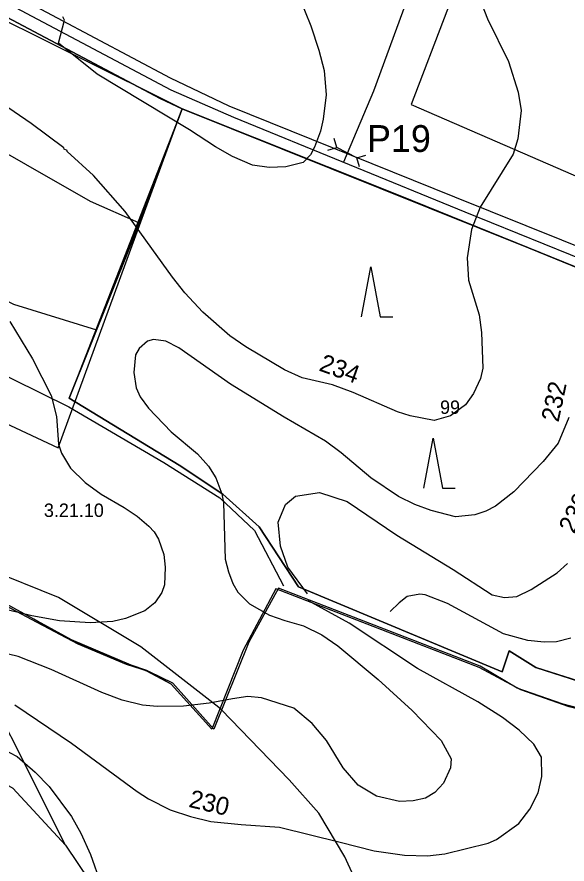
# Model space of a CAD drawing. Extents: x -662500 to -655523, y -1056000 to -1049993.
# Drawn here: x -659796.6 to -659489.3, y -1053594 to -1053120.4 of the extents above; entities that cross this region are included whole.
import ezdxf

# ---------------------------------------------------------------- set-up
doc = ezdxf.new("R2010")
doc.units = 0
for name, color, linetype in [('58', 7, 'Continuous'), ('63LINIE', 7, 'Continuous'), ('Vrstva 1', 7, 'Continuous'), ('Vrstva 15', 7, 'Continuous'), ('Vrstva 24', 7, 'Continuous'), ('Vrstva 37', 7, 'Continuous'), ('Vrstva 5', 7, 'Continuous'), ('Vrstva 61', 7, 'Continuous'), ('Vrstva 7', 7, 'Continuous'), ('Vrstva 9', 7, 'Continuous')]:
    doc.layers.add(name, color=color, linetype=linetype)

msp = doc.modelspace()

# ---------------------------------------------------------------- linework, layer by layer
at = {"layer": '58'}
msp.add_lwpolyline([(-659349.05, -1053610.31), (-659382.28, -1053593.05), (-659417.22, -1053580.42), (-659433.92, -1053582.96), (-659461.02, -1053573.16), (-659482.43, -1053565.41), (-659473.54, -1053538.79), (-659468.08, -1053510.71), (-659491.48, -1053504.57), (-659517.22, -1053495.65), (-659537.81, -1053483.36), (-659650.49, -1053439.77), (-659667.03, -1053469.94), (-659686.62, -1053518.64), (-659709.63, -1053492.85), (-659722.57, -1053486.62), (-659735.51, -1053482.41), (-659762.47, -1053471.11), (-659788.5, -1053457.32), (-659816.61, -1053442.42)], dxfattribs=at)
at = {"layer": '63LINIE'}
msp.add_lwpolyline([(-660157.65, -1052847.13), (-660132.52, -1052869.51), (-660111.66, -1052892.24), (-660084.95, -1052921), (-660069.74, -1052937.89), (-660023.99, -1052984.81), (-660006.51, -1053000.13), (-659985.6, -1053013.28), (-659850.42, -1053086.91), (-659781.9, -1053123.24), (-659710.72, -1053161.03), (-659675.58, -1053176.35), (-659546.48, -1053229.26), (-659428.67, -1053277.07), (-659332.46, -1053315.26), (-659288.19, -1053334.01)], dxfattribs=at)
at = {"layer": 'Vrstva 1'}
for points in [[(-659408.81, -1053315), (-659357.31, -1053379.54), (-659371.42, -1053421.26), (-659397.36, -1053408.04), (-659415.14, -1053443.98), (-659395.43, -1053476.68), (-659396.96, -1053511.86), (-659473.07, -1053494.87), (-659506.81, -1053484.14), (-659521.74, -1053474.81), (-659525.6, -1053486.6), (-659639.42, -1053438.92), (-659661.41, -1053405.48), (-659681.61, -1053387.18), (-659705.99, -1053371.05), (-659767.42, -1053333.48), (-659733.08, -1053247.59), (-659704.27, -1053171.81)], [(-659704.27, -1053171.81), (-659649.81, -1053193.58), (-659510.84, -1053249.48), (-659447.27, -1053275.33), (-659454.8, -1053293.04), (-659408.81, -1053315)], [(-659352.7, -1053608.59), (-659382.31, -1053593.57), (-659400.19, -1053586.69), (-659419.88, -1053580.04), (-659433.72, -1053582.64), (-659469.23, -1053570.77), (-659483.99, -1053565.83), (-659475.92, -1053539.11), (-659469.8, -1053510.83), (-659488.11, -1053506.12), (-659515.11, -1053496.67), (-659538.49, -1053484.19), (-659651.93, -1053440.19), (-659670.2, -1053474.39), (-659687.83, -1053518.62), (-659710.54, -1053493.35), (-659724.05, -1053486.09), (-659732.76, -1053482.89), (-659763.85, -1053469.82), (-659766.11, -1053468.58), (-659784.94, -1053458.3), (-659787.26, -1053457.03), (-659804.8, -1053447.45)]]:
    msp.add_lwpolyline(points, dxfattribs=at)
at = {"layer": 'Vrstva 15'}
for points in [[(-659491.47, -1052600.22), (-659560.64, -1052733.92), (-659579.45, -1052789.58), (-659610.72, -1052846.89), (-659556.93, -1052891.69), (-659532.56, -1052924.18), (-659546.19, -1053014.6), (-659577.15, -1053106.27), (-659597.46, -1053161.91), (-659614.21, -1053201.5)], [(-660065.03, -1053195.42), (-659955.25, -1053245.75), (-659767.64, -1053338.31), (-659714.66, -1053369.5), (-659683.23, -1053389.22), (-659663.87, -1053407.49), (-659647.8, -1053438.49)]]:
    msp.add_lwpolyline(points, dxfattribs=at)
at = {"layer": 'Vrstva 24'}
for points in [[(-659728.49, -1053235.51), (-659755.5, -1053223.5), (-659901.5, -1053140), (-659970.5, -1053087.5), (-659990.5, -1053068), (-660000, -1053060.67), (-660008, -1053054.5), (-660026.5, -1053036.5), (-660039.5, -1053009.5), (-660040.38, -1053000), (-660042, -1052982.5), (-660034, -1052954)], [(-660081, -1053315.5), (-660096, -1053300), (-660112, -1053273), (-660119.5, -1053246), (-660118.5, -1053214.5), (-660111.5, -1053187.5), (-660090.5, -1053151.5), (-660075, -1053138), (-660060, -1053131), (-660044.5, -1053128), (-660018, -1053135), (-660007, -1053141.5), (-660000, -1053147.33), (-659995, -1053151.5), (-659934, -1053205.5), (-659879, -1053241.5), (-659798.5, -1053281), (-659752.13, -1053295.23)], [(-659728.49, -1053235.51), (-659704.27, -1053171.81), (-659510.84, -1053249.48), (-659447.27, -1053275.33), (-659454.8, -1053293.04), (-659408.81, -1053315), (-659357.31, -1053379.54)], [(-659752.13, -1053295.23), (-659733.08, -1053247.59), (-659728.49, -1053235.51)], [(-659478.7, -1053493.08), (-659506.81, -1053484.14), (-659521.74, -1053474.81), (-659525.6, -1053486.6), (-659639.42, -1053438.92), (-659661.41, -1053405.48), (-659681.61, -1053387.18), (-659705.99, -1053371.05), (-659767.42, -1053333.48), (-659752.13, -1053295.23)], [(-659547, -1053857), (-659553, -1053835), (-659577.5, -1053700), (-659592, -1053637), (-659613.5, -1053590), (-659628, -1053565.5), (-659644.5, -1053547), (-659682.5, -1053507.5), (-659683.92, -1053506.4), (-659727.5, -1053472.5), (-659773.5, -1053445), (-659853, -1053413), (-659885, -1053404.5)], [(-659769.5, -1053583.5), (-659830.5, -1053462), (-659842, -1053442.5), (-659850.5, -1053432.5), (-659861, -1053420.5), (-659881.56, -1053406.8), (-659885, -1053404.5)], [(-660267, -1053453), (-660245, -1053457.5), (-660181.5, -1053447.5), (-660160, -1053446.5), (-660126.5, -1053449), (-660086, -1053456), (-660070, -1053459.5), (-660043.5, -1053470), (-660010, -1053485.5), (-660000, -1053490.5), (-659990, -1053495.5), (-659964, -1053526), (-659956.84, -1053531.01), (-659954, -1053533), (-659924.5, -1053540.5), (-659867, -1053533), (-659839, -1053534), (-659815, -1053542.5), (-659799, -1053551.5), (-659769.5, -1053583.5)], [(-659769.5, -1053583.5), (-659703.5, -1053681.5), (-659687, -1053701.5)]]:
    msp.add_lwpolyline(points, dxfattribs=at)
at = {"layer": 'Vrstva 37'}
for points in [[(-660026.32, -1052991.73), (-660026.32, -1053058.37), (-660035.43, -1053154.64), (-660050.23, -1053231.54), (-659773.69, -1053361.27), (-659704.27, -1053171.81), (-659884.58, -1053081.65)], [(-659536.53, -1053064.71), (-659576.38, -1053169.38), (-659333.28, -1053275.05), (-659323.04, -1053211.82), (-659365.73, -1053099.03)]]:
    msp.add_lwpolyline(points, close=True, dxfattribs=at)
at = {"layer": 'Vrstva 5'}
for points in [[(-659937.32, -1052850.73), (-659969.58, -1052873.81), (-659986.59, -1052886.79), (-659995.64, -1052898.4), (-660031.07, -1052952.12), (-660039.24, -1052962.1), (-660004.2, -1052995.1), (-659978.55, -1053011.07), (-659877.72, -1053065.47), (-659795.26, -1053109.44), (-659710.99, -1053154.41), (-659678.33, -1053170.13), (-659552.14, -1053220.98), (-659353.83, -1053300.67), (-659328.92, -1053309.76), (-659307.52, -1053281.7), (-659380.3, -1053101.02), (-659414.22, -1052998.59), (-659429.64, -1052959.69), (-659439.55, -1052923.56), (-659442.36, -1052874.55), (-659444.11, -1052845.81)], [(-659877.72, -1053065.47), (-659795.26, -1053109.44), (-659710.99, -1053154.41), (-659678.33, -1053170.13), (-659552.14, -1053220.98), (-659353.83, -1053300.67), (-659328.92, -1053309.76), (-659331.19, -1053313.18), (-659314.63, -1053326.76), (-659289.39, -1053339.57), (-659294.69, -1053337.55), (-659360.48, -1053311.02), (-659451.61, -1053273.55), (-659582.56, -1053220.47), (-659704.27, -1053171.81), (-659716.54, -1053165.89), (-659802.22, -1053120.51)], [(-659802.22, -1053120.51), (-659716.54, -1053165.89), (-659704.27, -1053171.81), (-659767.42, -1053333.48), (-659705.99, -1053371.05), (-659681.61, -1053387.18), (-659661.41, -1053405.48), (-659639.42, -1053438.92), (-659525.6, -1053486.6), (-659521.74, -1053474.81), (-659506.81, -1053484.14), (-659473.07, -1053494.87)], [(-659604.21, -1053288.05), (-659598.96, -1053260.05), (-659593.71, -1053288.05), (-659586.71, -1053288.05)], [(-659354.31, -1053607.7), (-659382.31, -1053593.57), (-659419.88, -1053580.04), (-659433.72, -1053582.64), (-659483.99, -1053565.83), (-659475.92, -1053539.11), (-659469.8, -1053510.83), (-659488.11, -1053506.12), (-659515.11, -1053496.67), (-659538.49, -1053484.19), (-659651.93, -1053440.19), (-659670.2, -1053474.39), (-659687.83, -1053518.62), (-659710.54, -1053493.35), (-659724.01, -1053485.82), (-659732.76, -1053482.89), (-659766.11, -1053468.58), (-659838.26, -1053429.18)]]:
    msp.add_lwpolyline(points, dxfattribs=at)
msp.add_lwpolyline([(-659704.27, -1053171.81), (-659733.08, -1053247.59), (-659767.42, -1053333.48), (-659705.99, -1053371.05), (-659681.61, -1053387.18), (-659661.41, -1053405.48), (-659639.42, -1053438.92), (-659525.6, -1053486.6), (-659521.74, -1053474.81), (-659506.81, -1053484.14), (-659473.07, -1053494.87), (-659428.79, -1053504.91), (-659396.96, -1053511.86), (-659395.43, -1053476.68), (-659415.14, -1053443.98), (-659397.36, -1053408.04), (-659371.42, -1053421.26), (-659357.31, -1053379.54), (-659408.81, -1053315), (-659454.8, -1053293.04), (-659447.27, -1053275.33), (-659451.61, -1053273.55), (-659510.84, -1053249.48), (-659582.56, -1053220.47)], close=True, dxfattribs=at)
at = {"layer": 'Vrstva 61'}
for points in [[(-659622.91, -1053194.86), (-659617.84, -1053193.31), (-659619.39, -1053188.24)], [(-659606.81, -1053199.18), (-659617.84, -1053193.31)], [(-659605.26, -1053204.26), (-659606.81, -1053199.18), (-659601.73, -1053197.63)]]:
    msp.add_lwpolyline(points, dxfattribs=at)
at = {"layer": 'Vrstva 7'}
for p, q in [((-659638.85, -1053109.45), (-659632.47, -1053125.32)), ((-659537.19, -1053112.86), (-659533.77, -1053121.4)), ((-659773.39, -1053135.1), (-659770.08, -1053122.21)), ((-659770.08, -1053122.21), (-659771.07, -1053120.22)), ((-659533.77, -1053121.4), (-659521.95, -1053145.32)), ((-659632.47, -1053125.32), (-659627.94, -1053138.93)), ((-659751.86, -1053152.33), (-659773.39, -1053135.1)), ((-659627.94, -1053138.93), (-659625.1, -1053150.27)), ((-659521.95, -1053145.32), (-659516.55, -1053162.41)), ((-659625.1, -1053150.27), (-659623.97, -1053163.87)), ((-659700.21, -1053183.43), (-659751.86, -1053152.33)), ((-659623.97, -1053163.87), (-659625.53, -1053177.48)), ((-659516.55, -1053162.41), (-659514.98, -1053172.66)), ((-659788.65, -1053179.88), (-659804.66, -1053168.97)), ((-659514.98, -1053172.66), (-659516.83, -1053188.6)), ((-659770.36, -1053193.63), (-659788.65, -1053179.88)), ((-659625.53, -1053177.48), (-659627.09, -1053184.28)), ((-659685.76, -1053193.06), (-659700.21, -1053183.43)), ((-659627.09, -1053184.28), (-659630.35, -1053193.21)), ((-659516.83, -1053188.6), (-659519.39, -1053197.15)), ((-659770.22, -1053194.34), (-659770.36, -1053193.63)), ((-659768.52, -1053195.05), (-659770.22, -1053194.34)), ((-659676.26, -1053198.45), (-659685.76, -1053193.06)), ((-659630.35, -1053193.21), (-659632.61, -1053197.46)), ((-659768.52, -1053195.61), (-659768.52, -1053195.05)), ((-659753.78, -1053208.94), (-659768.52, -1053195.61)), ((-659665.07, -1053203.27), (-659676.26, -1053198.45)), ((-659632.61, -1053197.46), (-659636.72, -1053201.71)), ((-659519.39, -1053197.15), (-659537.89, -1053226.66)), ((-659655.71, -1053204.54), (-659665.07, -1053203.27)), ((-659646.36, -1053204.12), (-659655.71, -1053204.54)), ((-659636.72, -1053201.71), (-659646.36, -1053204.12)), ((-659736.21, -1053229.06), (-659753.78, -1053208.94)), ((-659537.89, -1053226.66), (-659542.74, -1053239.28)), ((-659709.71, -1053265.91), (-659736.21, -1053229.06)), ((-659542.74, -1053239.28), (-659545.17, -1053255)), ((-659545.17, -1053255), (-659544.42, -1053267.55)), ((-659702.77, -1053274.69), (-659709.71, -1053265.91)), ((-659544.42, -1053267.55), (-659538.47, -1053286.85)), ((-659692.84, -1053285.46), (-659702.77, -1053274.69)), ((-659677.68, -1053298.64), (-659692.84, -1053285.46)), ((-659538.47, -1053286.85), (-659537.05, -1053296.81)), ((-659800.55, -1053290.56), (-659787.94, -1053311.54)), ((-659668.75, -1053304.88), (-659677.68, -1053298.64)), ((-659537.05, -1053296.81), (-659536.34, -1053316.75)), ((-659723.74, -1053301.62), (-659728.42, -1053305.73)), ((-659720.34, -1053300.77), (-659723.74, -1053301.62)), ((-659713.54, -1053301.62), (-659720.34, -1053300.77)), ((-659706.17, -1053305.45), (-659713.54, -1053301.62)), ((-659728.42, -1053305.73), (-659730.4, -1053309.27)), ((-659677.26, -1053325.71), (-659706.17, -1053305.45)), ((-659647.21, -1053317.63), (-659668.75, -1053304.88)), ((-659787.94, -1053311.54), (-659777.59, -1053331.95)), ((-659730.4, -1053309.27), (-659731.25, -1053319.19)), ((-659637.34, -1053322.07), (-659647.21, -1053317.63)), ((-659536.34, -1053316.75), (-659537.76, -1053322.44)), ((-659731.25, -1053319.19), (-659730.12, -1053327.7)), ((-659620.42, -1053326.14), (-659637.34, -1053322.07)), ((-659537.76, -1053322.44), (-659541.6, -1053330.98)), ((-659647.31, -1053344.11), (-659677.26, -1053325.71)), ((-659608.73, -1053330.35), (-659620.42, -1053326.14)), ((-659777.59, -1053331.95), (-659774.47, -1053343.85)), ((-659730.12, -1053327.7), (-659727.71, -1053332.8)), ((-659584.03, -1053341.09), (-659608.73, -1053330.35)), ((-659541.6, -1053330.98), (-659546.02, -1053337.25)), ((-659727.71, -1053332.8), (-659723.17, -1053339.03)), ((-659723.17, -1053339.03), (-659710.56, -1053352.35)), ((-659576.92, -1053343.37), (-659584.03, -1053341.09)), ((-659546.02, -1053337.25), (-659554.42, -1053343.37)), ((-659774.47, -1053343.85), (-659773.48, -1053359.16)), ((-659624.17, -1053357.63), (-659647.31, -1053344.11)), ((-659563.53, -1053346.08), (-659576.92, -1053343.37)), ((-659554.42, -1053343.37), (-659563.53, -1053346.08)), ((-659488.35, -1053344.37), (-659494.33, -1053358.61)), ((-659710.56, -1053352.35), (-659695.82, -1053364.68)), ((-659773.48, -1053359.16), (-659771.78, -1053364.26)), ((-659615.5, -1053364.02), (-659624.17, -1053357.63)), ((-659494.33, -1053358.61), (-659502.73, -1053369)), ((-659771.78, -1053364.26), (-659766.68, -1053372.62)), ((-659695.82, -1053364.68), (-659689.58, -1053371.63)), ((-659598.98, -1053377.97), (-659615.5, -1053364.02)), ((-659502.73, -1053369), (-659519.11, -1053385.94)), ((-659766.68, -1053372.62), (-659758.6, -1053380.7)), ((-659689.58, -1053371.63), (-659685.47, -1053378.15)), ((-659685.47, -1053378.15), (-659682.22, -1053386.93)), ((-659583.46, -1053388.51), (-659598.98, -1053377.97)), ((-659758.6, -1053380.7), (-659749.53, -1053387.22)), ((-659749.53, -1053387.22), (-659736.78, -1053394.58)), ((-659682.22, -1053386.93), (-659681.22, -1053392.03)), ((-659646.69, -1053392.98), (-659641.03, -1053388.3)), ((-659641.03, -1053388.3), (-659627.59, -1053386.3)), ((-659627.59, -1053386.3), (-659612.22, -1053391.21)), ((-659574.35, -1053393.06), (-659583.46, -1053388.51)), ((-659519.11, -1053385.94), (-659529.22, -1053393.92)), ((-659681.22, -1053392.03), (-659680.23, -1053423.5)), ((-659650.63, -1053402.82), (-659646.69, -1053392.98)), ((-659612.22, -1053391.21), (-659584.43, -1053410.16)), ((-659565.24, -1053396.34), (-659574.35, -1053393.06)), ((-659736.78, -1053394.58), (-659729.55, -1053399.51)), ((-659551.57, -1053399.9), (-659565.24, -1053396.34)), ((-659534.63, -1053396.76), (-659540.75, -1053398.76)), ((-659529.22, -1053393.92), (-659534.63, -1053396.76)), ((-659729.55, -1053399.51), (-659722.89, -1053405.07)), ((-659649.46, -1053416.23), (-659650.63, -1053402.82)), ((-659540.75, -1053398.76), (-659551.57, -1053399.9)), ((-659722.89, -1053405.07), (-659719.91, -1053408.33)), ((-659719.91, -1053408.33), (-659717.5, -1053412.3)), ((-659717.5, -1053412.3), (-659714.67, -1053420.94)), ((-659584.43, -1053410.16), (-659552.99, -1053429.37)), ((-659645.33, -1053428.1), (-659649.46, -1053416.23)), ((-659714.67, -1053420.94), (-659713.82, -1053428.03)), ((-659680.23, -1053423.5), (-659678.53, -1053430.58)), ((-659494.9, -1053431.22), (-659489.07, -1053425.95)), ((-659713.82, -1053428.03), (-659714.24, -1053437.95)), ((-659678.53, -1053430.58), (-659676.12, -1053437.05)), ((-659634.34, -1053443), (-659645.33, -1053428.1)), ((-659552.99, -1053429.37), (-659531.07, -1053443.46)), ((-659509.28, -1053440.47), (-659494.9, -1053431.22)), ((-659714.24, -1053437.95), (-659715.66, -1053442.2)), ((-659676.12, -1053437.05), (-659673.15, -1053441.92)), ((-659517.4, -1053444.32), (-659509.28, -1053440.47)), ((-659715.66, -1053442.2), (-659719.63, -1053448.01)), ((-659673.15, -1053441.92), (-659666.77, -1053448.44)), ((-659578.62, -1053444.32), (-659583.18, -1053448.02)), ((-659571.5, -1053443.18), (-659578.62, -1053444.32)), ((-659568.66, -1053443.46), (-659571.5, -1053443.18)), ((-659556.13, -1053448.3), (-659568.66, -1053443.46)), ((-659531.07, -1053443.46), (-659524.23, -1053445.03)), ((-659524.23, -1053445.03), (-659517.4, -1053444.32)), ((-659788.36, -1053455.24), (-659822.37, -1053447.02)), ((-659719.63, -1053448.01), (-659725.16, -1053452.41)), ((-659666.77, -1053448.44), (-659655.56, -1053454.9)), ((-659611.1, -1053459.29), (-659634.07, -1053446.57)), ((-659583.18, -1053448.02), (-659588.23, -1053452.83)), ((-659524.8, -1053465.25), (-659556.13, -1053448.3)), ((-659772.77, -1053458.07), (-659788.36, -1053455.24)), ((-659725.16, -1053452.41), (-659735.93, -1053456.8)), ((-659655.56, -1053454.9), (-659646.94, -1053457.85)), ((-659755.77, -1053459.21), (-659772.77, -1053458.07)), ((-659743.01, -1053458.36), (-659755.77, -1053459.21)), ((-659735.93, -1053456.8), (-659743.01, -1053458.36)), ((-659646.94, -1053457.85), (-659636.47, -1053460.89)), ((-659572.79, -1053484.61), (-659611.1, -1053459.29)), ((-659636.47, -1053460.89), (-659626.23, -1053465.89)), ((-659626.23, -1053465.89), (-659617.35, -1053471.94)), ((-659511.14, -1053468.95), (-659524.8, -1053465.25)), ((-659502.02, -1053469.95), (-659511.14, -1053468.95)), ((-659487.21, -1053467.67), (-659495.19, -1053469.8)), ((-659617.35, -1053471.94), (-659594.85, -1053490.73)), ((-659495.19, -1053469.8), (-659502.02, -1053469.95)), ((-659796.01, -1053478.05), (-659811.04, -1053474.37)), ((-659777.59, -1053485.28), (-659796.01, -1053478.05)), ((-659749.25, -1053498.04), (-659777.59, -1053485.28)), ((-659539.18, -1053503.26), (-659572.79, -1053484.61)), ((-659594.85, -1053490.73), (-659575.78, -1053508.1)), ((-659737.91, -1053502.29), (-659749.25, -1053498.04)), ((-659726.57, -1053505.12), (-659737.91, -1053502.29)), ((-659676.29, -1053501.56), (-659689.24, -1053504.08)), ((-659667.62, -1053500.3), (-659676.29, -1053501.56)), ((-659659.97, -1053501.16), (-659667.62, -1053500.3)), ((-659641.95, -1053506.85), (-659659.97, -1053501.16)), ((-659797.86, -1053504.98), (-659766.25, -1053526.38)), ((-659718.35, -1053505.97), (-659726.57, -1053505.12)), ((-659703.61, -1053505.69), (-659718.35, -1053505.97)), ((-659689.24, -1053504.08), (-659703.61, -1053505.69)), ((-659631.77, -1053515.37), (-659641.95, -1053506.85)), ((-659525.37, -1053512.09), (-659539.18, -1053503.26)), ((-659575.78, -1053508.1), (-659559.69, -1053524.91)), ((-659516.12, -1053519.07), (-659525.37, -1053512.09)), ((-659623.76, -1053524.91), (-659631.77, -1053515.37)), ((-659507.86, -1053526.9), (-659516.12, -1053519.07)), ((-659614.36, -1053540.28), (-659623.76, -1053524.91)), ((-659559.69, -1053524.91), (-659553.99, -1053535.16)), ((-659805.08, -1053529.36), (-659796.58, -1053533.89)), ((-659766.25, -1053526.38), (-659729.55, -1053553.45)), ((-659503.59, -1053534.3), (-659507.86, -1053526.9)), ((-659796.58, -1053533.89), (-659786.38, -1053542.54)), ((-659553.99, -1053535.16), (-659554.42, -1053540.28)), ((-659503.45, -1053545.12), (-659503.59, -1053534.3)), ((-659605.96, -1053549.82), (-659614.36, -1053540.28)), ((-659554.42, -1053540.28), (-659558.41, -1053548.83)), ((-659786.38, -1053542.54), (-659778.58, -1053550.61)), ((-659505.44, -1053554.24), (-659503.45, -1053545.12)), ((-659595.71, -1053556.09), (-659605.96, -1053549.82)), ((-659558.41, -1053548.83), (-659563.25, -1053553.95)), ((-659778.58, -1053550.61), (-659766.25, -1053567.48)), ((-659729.55, -1053553.45), (-659723.17, -1053557.56)), ((-659563.25, -1053553.95), (-659568.37, -1053557.08)), ((-659510.14, -1053563.35), (-659505.44, -1053554.24)), ((-659723.17, -1053557.56), (-659710.98, -1053563.65)), ((-659582.9, -1053559.08), (-659595.71, -1053556.09)), ((-659575.21, -1053558.65), (-659582.9, -1053559.08)), ((-659568.37, -1053557.08), (-659575.21, -1053558.65)), ((-659710.98, -1053563.65), (-659699.65, -1053567.48)), ((-659516.26, -1053571.32), (-659510.14, -1053563.35)), ((-659766.25, -1053567.48), (-659761.01, -1053576.83)), ((-659699.65, -1053567.48), (-659688.31, -1053570.17)), ((-659688.31, -1053570.17), (-659671.3, -1053571.87)), ((-659671.3, -1053571.87), (-659649.88, -1053573.46)), ((-659649.88, -1053573.46), (-659616.05, -1053581.72)), ((-659528.65, -1053580.29), (-659516.26, -1053571.32)), ((-659761.01, -1053576.83), (-659755.48, -1053588.74)), ((-659616.05, -1053581.72), (-659597.13, -1053586.7)), ((-659557.55, -1053588.27), (-659533.35, -1053582.28)), ((-659533.35, -1053582.28), (-659528.65, -1053580.29)), ((-659597.13, -1053586.7), (-659580.05, -1053589.12)), ((-659755.48, -1053588.74), (-659738.76, -1053636.35)), ((-659580.05, -1053589.12), (-659567.23, -1053589.4)), ((-659567.23, -1053589.4), (-659557.55, -1053588.27))]:
    msp.add_line(p, q, dxfattribs=at)
at = {"layer": 'Vrstva 9'}
msp.add_lwpolyline([(-659569.39, -1053383.8), (-659564.14, -1053355.8), (-659558.89, -1053383.8), (-659551.89, -1053383.8)], dxfattribs=at)

# ---------------------------------------------------------------- texts
at = {"layer": 'Vrstva 24'}
for s, p in [('99', (-659560.27, -1053342.33)), ('3.21.10', (-659781.57, -1053399.94))]:
    msp.add_text(s, height=7.5, dxfattribs=at).set_placement(p)
at = {"layer": 'Vrstva 61'}
msp.add_text('P19', height=15, dxfattribs=at).set_placement((-659601.08, -1053195.85))
at = {"layer": 'Vrstva 7'}
for s, rotation, p in [('234', 340.202, (-659628.41, -1053317.95)), ('232', 78.0059, (-659494.09, -1053347.28)), ('230', 64.6748, (-659485.41, -1053409.76)), ('230', 346.6424, (-659701.12, -1053561.99))]:
    msp.add_text(s, height=10, rotation=rotation, dxfattribs=at).set_placement(p)

doc.saveas('drawing.dxf')
